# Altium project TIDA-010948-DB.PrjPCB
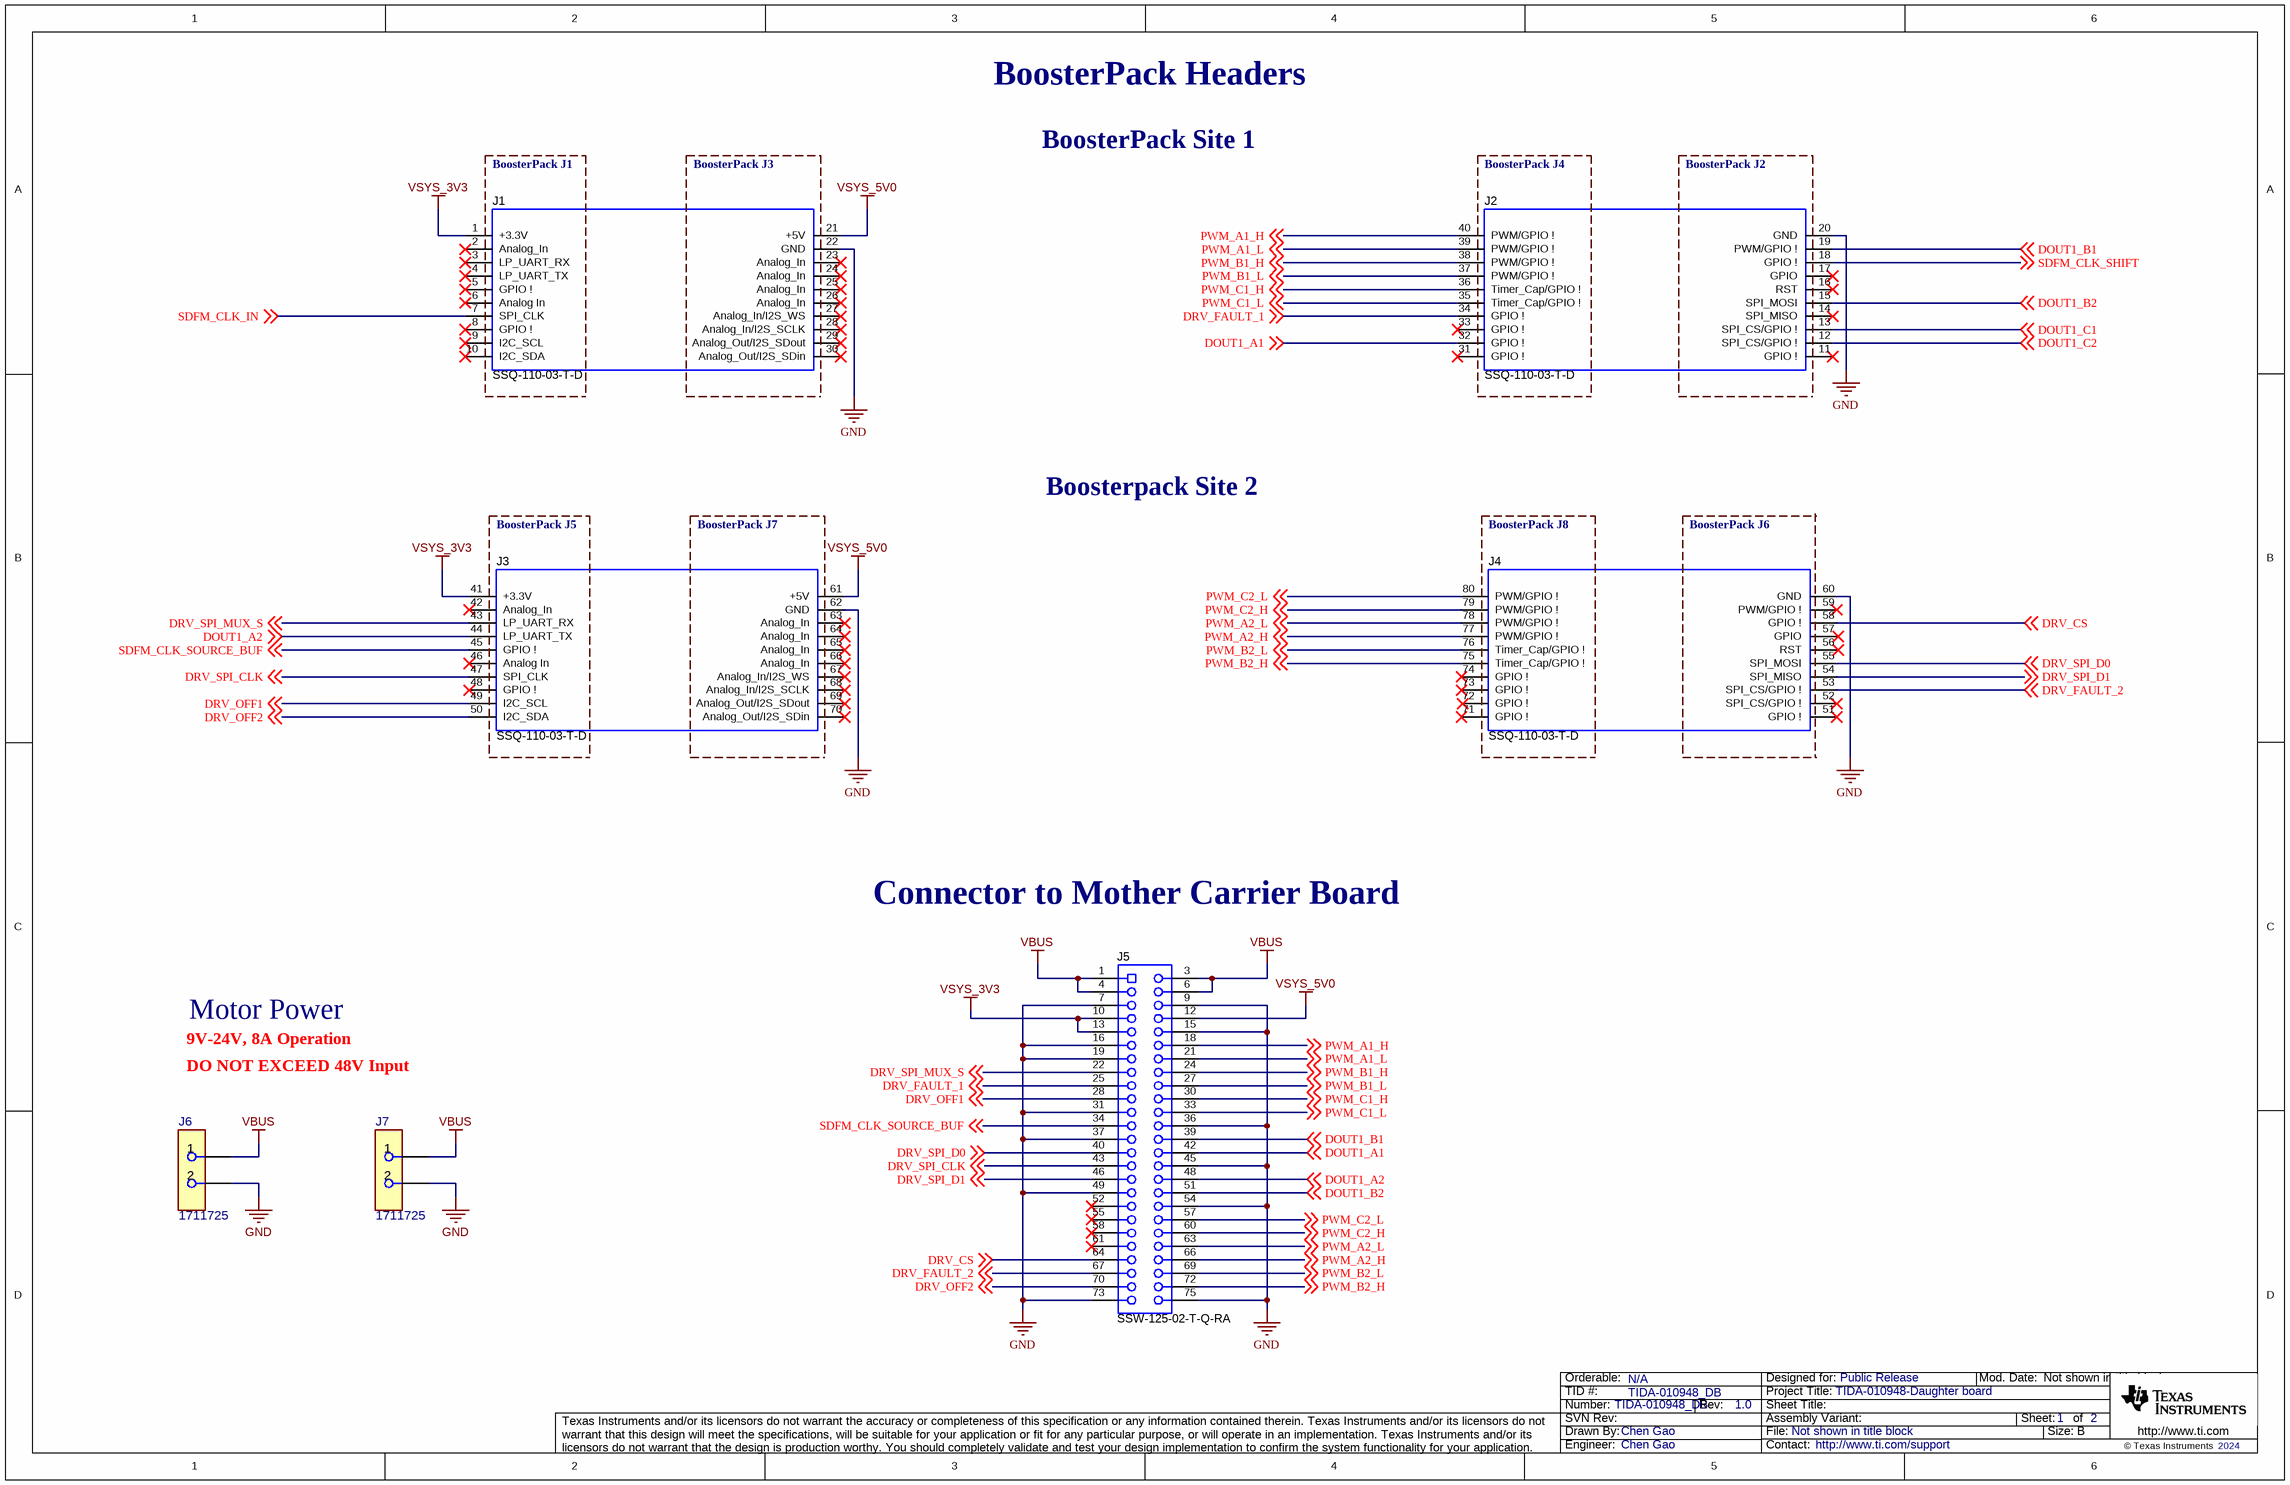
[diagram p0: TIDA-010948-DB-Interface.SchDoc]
EVM_orderable: N/A; DrawnBy: Chen Gao; TID: TIDA-010948_DB; TechSupport: http://www.ti.com/support; SCH_Rev: 1.0; PRJ_Title: TIDA-010948-Daughter board; PRJ_Number: TIDA-010948_DB; PRJ_Engineer: Chen Gao; PRJ_Customer: Public Release; PCB_Rev: 1.0; PCB_Layout: TIDA-010948_DB; CopyrightYear: 2024
2 sheets, 17 parts. Net scope: global (net labels, ports and power ports of the same name join across sheets).
Board file: TIDA-010948-DB.PcbDoc
Sheets:
  TIDA-010948-DB-Interface.SchDoc
  TIDA-010948-DB-Hardware.SchDoc

## Sheet TIDA-010948-DB-Interface.SchDoc
size 431 x 279 mm; Date: Not shown in title block; ApprovedBy: Not shown in title block; CheckedBy: Not shown in title block; Author: Not shown in title block; CompanyName: Not shown in title block; Engineer: Not shown in title block; Organization: Not shown in title block; Address1: Not shown in title block; Address2: Not shown in title block; Address3: Not shown in title block; Address4: Not shown in title block; DocumentNumber: 2; Revision: Use project parameter SCH_Rev; SheetNumber: 1; SheetTotal: 2; PageSetup: Record=PageOptions¦CenterHorizontal=True¦CenterVertical=True¦PrintScale=1.00¦XCorrection=1.00¦YCorrection=1.00¦PrintKind=0¦BorderSize=5000000¦LeftOffset=0¦BottomOffset=0¦Orientation=2¦PaperLength=1000¦PaperWidth=1000¦Scale=100¦PaperSource=15¦PrintQuality=600¦MediaType=1¦DitherType=10¦PaperKind=Letter¦PrintScaleMode=1

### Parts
J1  SSQ-110-03-T-D  [BoosterPack_40pin_J1J3]
J2  SSQ-110-03-T-D  [BoosterPack_40pin_J2J4]
J3  SSQ-110-03-T-D  [BoosterPack_40pin_J5J7]
J4  SSQ-110-03-T-D  [BoosterPack_40pin_J6J8]
J5  SSW-125-02-T-Q-RA  [Samtec_SSW-125-02-T-Q-RA]
J6  1711725  [FP-1888687_HDR2-MFG]
J7  1711725  [FP-1888687_HDR2-MFG]

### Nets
GND: J1.22(GND) J2.20(GND) J3.62(GND) J4.60(GND) J5.7 J5.9 J5.15 J5.16 J5.19 J5.31 J5.36 J5.37 J5.45 J5.49 J5.54 J5.73 J5.75 J6.2 J7.2
VBUS: J5.1 J5.3 J5.4 J5.6 J6.1 J7.1
VSYS_3V3: J1.1(+3.3V) J3.41(+3.3V) J5.10 J5.13
VSYS_5V0: J1.21(+5V) J3.61(+5V) J5.12
DOUT1_A1: J2.32(GPIO_!) J5.42 ; off-sheet DOUT1_A1
DOUT1_A2: J3.44(LP_UART_TX) J5.48 ; off-sheet DOUT1_A2
DOUT1_B1: J2.19(PWM/GPIO_!) J5.39 ; off-sheet DOUT1_B1
DOUT1_B2: J2.15(SPI_MOSI) J5.51 ; off-sheet DOUT1_B2
DOUT1_C1: J2.13(SPI_CS/GPIO_!) ; off-sheet DOUT1_C1
DOUT1_C2: J2.12(SPI_CS/GPIO_!) ; off-sheet DOUT1_C2
DRV_CS: J4.58(GPIO_!) J5.64 ; off-sheet DRV_CS
DRV_FAULT_1: J2.34(GPIO_!) J5.25 ; off-sheet DRV_FAULT_1
DRV_FAULT_2: J4.53(SPI_CS/GPIO_!) J5.67 ; off-sheet DRV_FAULT_2
DRV_OFF1: J3.49(I2C_SCL) J5.28 ; off-sheet DRV_OFF1
DRV_OFF2: J3.50(I2C_SDA) J5.70 ; off-sheet DRV_OFF2
DRV_SPI_CLK: J3.47(SPI_CLK) J5.43 ; off-sheet DRV_SPI_CLK
DRV_SPI_D0: J4.55(SPI_MOSI) J5.40 ; off-sheet DRV_SPI_D0
DRV_SPI_D1: J4.54(SPI_MISO) J5.46 ; off-sheet DRV_SPI_D1
DRV_SPI_MUX_S: J3.43(LP_UART_RX) J5.22 ; off-sheet DRV_SPI_MUX_S
PWM_A1_H: J2.40(PWM/GPIO_!) J5.18 ; off-sheet PWM_A1_H
PWM_A1_L: J2.39(PWM/GPIO_!) J5.21 ; off-sheet PWM_A1_L
PWM_A2_H: J4.77(PWM/GPIO_!) J5.66 ; off-sheet PWM_A2_H
PWM_A2_L: J4.78(PWM/GPIO_!) J5.63 ; off-sheet PWM_A2_L
PWM_B1_H: J2.38(PWM/GPIO_!) J5.24 ; off-sheet PWM_B1_H
PWM_B1_L: J2.37(PWM/GPIO_!) J5.27 ; off-sheet PWM_B1_L
PWM_B2_H: J4.75(Timer_Cap/GPIO_!) J5.72 ; off-sheet PWM_B2_H
PWM_B2_L: J4.76(Timer_Cap/GPIO_!) J5.69 ; off-sheet PWM_B2_L
PWM_C1_H: J2.36(Timer_Cap/GPIO_!) J5.30 ; off-sheet PWM_C1_H
PWM_C1_L: J2.35(Timer_Cap/GPIO_!) J5.33 ; off-sheet PWM_C1_L
PWM_C2_H: J4.79(PWM/GPIO_!) J5.60 ; off-sheet PWM_C2_H
PWM_C2_L: J4.80(PWM/GPIO_!) J5.57 ; off-sheet PWM_C2_L
SDFM_CLK_IN: J1.7(SPI_CLK) ; off-sheet SDFM_CLK_IN
SDFM_CLK_SHIFT: J2.18(GPIO_!) ; off-sheet SDFM_CLK_SHIFT
SDFM_CLK_SOURCE_BUF: J3.45(GPIO_!) J5.34 ; off-sheet SDFM_CLK_SOURCE_BUF

Not connected (* = marked no-connect by the designer): J1 2(Analog_In)* 3(LP_UART_RX)* 4(LP_UART_TX)* 5(GPIO_!)* 6(Analog_In)* 8(GPIO_!)* 9(I2C_SCL)* 10(I2C_SDA)* 23(Analog_In)* 24(Analog_In)* 25(Analog_In)* 26(Analog_In)* 27(Analog_In/I2S_WS)* 28(Analog_In/I2S_SCLK)* 29(Analog_Out/I2S_SDout)* 30(Analog_Out/I2S_SDin)*; J2 11(GPIO_!)* 14(SPI_MISO)* 16(RST)* 17(GPIO)* 31(GPIO_!)* 33(GPIO_!)*; J3 42(Analog_In)* 46(Analog_In)* 48(GPIO_!)* 63(Analog_In)* 64(Analog_In)* 65(Analog_In)* 66(Analog_In)* 67(Analog_In/I2S_WS)* 68(Analog_In/I2S_SCLK)* 69(Analog_Out/I2S_SDout)* 70(Analog_Out/I2S_SDin)*; J4 51(GPIO_!)* 52(SPI_CS/GPIO_!)* 56(RST) 57(GPIO) 59(PWM/GPIO_!)* 71(GPIO_!)* 72(GPIO_!) 73(GPIO_!)* 74(GPIO_!)*; J5 52* 55* 58* 61*

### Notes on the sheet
- BoosterPack Headers
- BoosterPack J1
- BoosterPack J3
- BoosterPack Site 1
- BoosterPack J4
- BoosterPack J2
- Boosterpack Site 2
- BoosterPack J5
- BoosterPack J7
- BoosterPack J8
- BoosterPack J6
- Connector to Mother Carrier Board
- Motor Power
- 9V-24V, 8A Operation
- DO NOT EXCEED 48V Input

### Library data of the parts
J1 = CMP-0003837-4: Receptacle, 2.54mm, 10x2, Tin, TH; Alternate PartNumber: CRD-081413-A-G; Manufacturer: Samtec; Alternate Manufacturer: Major League Electronics; Note: Booster Pack 40 pin J1 and J3; Green_Lifecycle: Active; Green_REACh: Incomplete
J2 = CMP-0078266-4: Receptacle, 2.54mm, 10x2, Tin, TH; Alternate PartNumber: CRD-081413-A-G; Manufacturer: Samtec; Alternate Manufacturer: Major League Electronics; Note: Booster Pack 40 pin J2 and J4; Green_REACh: Incomplete; Green_Lifecycle: Active
J3 = CMP-0081070-3: Receptacle, 2.54mm, 10x2, Tin, TH; Alternate PartNumber: CRD-081413-A-G; Manufacturer: Samtec; Alternate Manufacturer: Major League Electronics; Note: Booster Pack 40 pin J5 and J7; Green_REACh: Incomplete; Green_Lifecycle: Active
J4 = CMP-0081071-3: Receptacle, 2.54mm, 10x2, Tin, TH; Alternate PartNumber: CRD-081413-A-G; Manufacturer: Samtec; Alternate Manufacturer: Major League Electronics; Note: Booster Pack 40 pin J6 and J8; Green_REACh: Incomplete; Green_Lifecycle: Active
J5 = CMP-0055988-1: Receptacle, 100mil, 25x2, R/A, TIN, TH; Manufacturer: Samtec; CT: FALSE
J6 J7 = CMP-0087130-1: Manufacturer: Phoenix Contact; Voltage_V: 400V; Current_A: 15A; Row_Count: 1; ContactFinish: Tin

## Sheet TIDA-010948-DB-Hardware.SchDoc
size 431 x 279 mm; Date: Not shown in title block; ApprovedBy: Not shown in title block; CheckedBy: Not shown in title block; Author: Not shown in title block; CompanyName: Not shown in title block; Engineer: Not shown in title block; Organization: Not shown in title block; Address1: Not shown in title block; Address2: Not shown in title block; Address3: Not shown in title block; Address4: Not shown in title block; DocumentNumber: 2; Revision: Use project parameter SCH_Rev; SheetNumber: 2; SheetTotal: 2; PageSetup: Record=PageOptions¦CenterHorizontal=True¦CenterVertical=True¦PrintScale=1.00¦XCorrection=1.00¦YCorrection=1.00¦PrintKind=0¦BorderSize=5000000¦LeftOffset=0¦BottomOffset=0¦Orientation=2¦PaperLength=1000¦PaperWidth=1000¦Scale=100¦PaperSource=15¦PrintQuality=600¦MediaType=1¦DitherType=10¦PaperKind=Letter¦PrintScaleMode=1
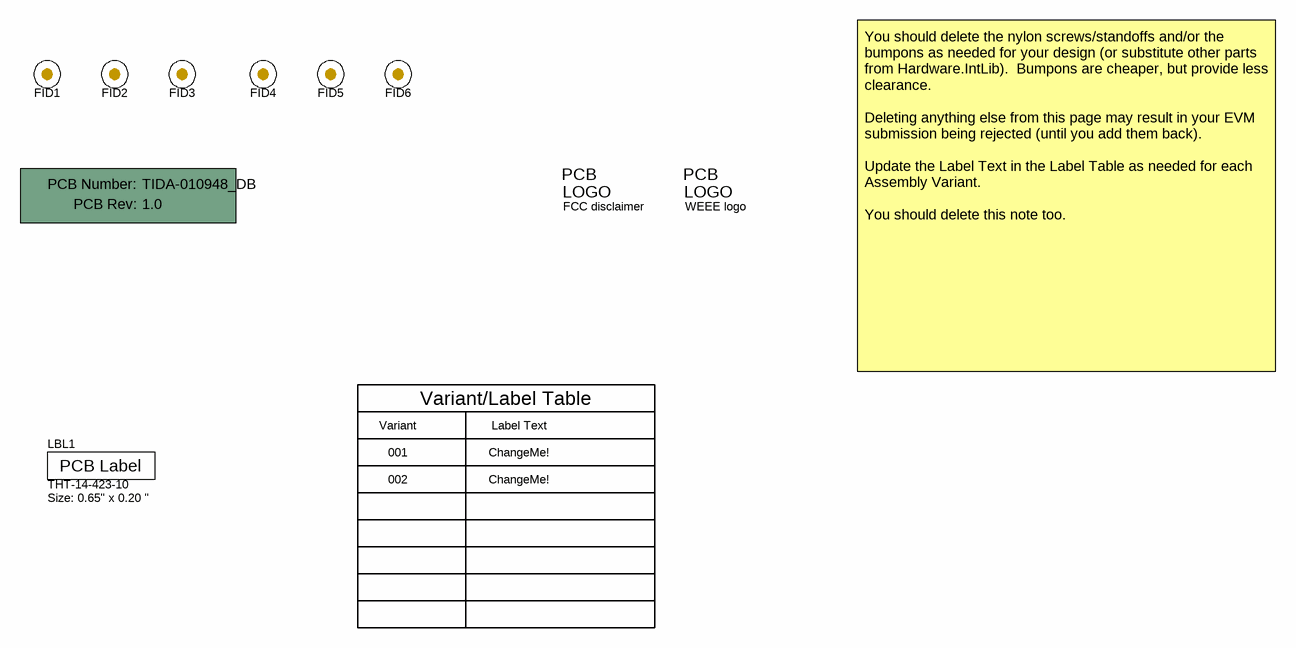
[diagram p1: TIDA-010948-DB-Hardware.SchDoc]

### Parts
!PCB1  Printed Circuit Board  (value not drawn)  (mechanical)
FID1  Fiducial  [Fiducial10-20]  (value not drawn)
FID2  Fiducial  [Fiducial10-20]  (value not drawn)
FID3  Fiducial  [Fiducial10-20]  (value not drawn)
FID4  Fiducial  [Fiducial10-20]  (value not drawn)
FID5  Fiducial  [Fiducial10-20]  (value not drawn)
FID6  Fiducial  [Fiducial10-20]  (value not drawn)
LBL1  THT-14-423-10  Note: Size: 0.65" x 0.20 "  [Label_650x200]
Logo2  FCC disclaimer  [FCC_disclaimer]  (no BOM)
Logo3  WEEE logo  [WEEE_Minimum]  (no BOM)

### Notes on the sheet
- Variant
- Variant/Label Table
- Label Text
- You should delete the nylon screws/standoffs and/or the bumpons as needed for your design (or substitute other parts from Hardware.IntLib).  Bumpons are cheaper, but provide less clearance.
  Deleting anything else from this page may result in your EVM submission being rejected (until you add them back).
  Update the Label Text in the Label Table as needed for each Assembly Variant.
  You should delete this note too.
- 001
- 002
- ChangeMe!

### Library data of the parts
!PCB1 = CMP-0003618-2: Manufacturer: Any; PartNumber: TIDA-010948_DB
FID1-FID6 = CMP-0077181-1: Fiducial mark.  There is nothing to buy or mount.
LBL1 = CMP-0003625-1: Thermal Transfer Printable Labels, 0.650" W x 0.200" H - 10,000 per roll; Manufacturer: Brady; CompType: Label
Logo2 = CMP-0074847-1: FCC_disclaimer; Library Reference: Logo
Logo3 = CMP-0074769-1

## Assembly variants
Variant of TIDA-010948-DB: not fitted FID1 FID2 FID3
